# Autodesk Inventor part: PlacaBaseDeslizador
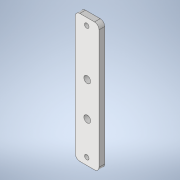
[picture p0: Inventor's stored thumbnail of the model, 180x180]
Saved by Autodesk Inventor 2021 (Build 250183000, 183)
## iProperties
Created: 2021-02
Part Number: PlacaBaseDeslizador
Material: Genérico
Document SubType Name: Modeling
Designer: ATOUZA
Density: 1 g/cm^3
Appearance: Valor por defecto
Author: ATOUZA
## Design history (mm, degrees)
node "Plano de trabajo1"
sketch "Boceto1"
  geometry: L1 (6.426, -37)-(6.426, 37) reference; L2 (5.426, 38)-(0.676, 38) reference; L3 (0.676, 38)-(0.676, 36.1) reference; L4 (0.676, 36.1)-(1.926, 36.1) reference; L5 (1.926, 36.1)-(1.926, 33.4) reference; L6 (1.926, 33.4)-(-4.074, 33.4) reference; L7 (-4.074, 33.4)-(-4.074, 36.1) reference; L8 (-4.074, 36.1)-(-2.824, 36.1) reference; L9 (-2.824, 36.1)-(-2.824, 38) reference; L10 (-2.824, 38)-(-5.074, 38) reference; L11 (-6.074, 37)-(-6.074, -37) reference; L12 (-5.074, -38)-(-2.824, -38) reference; L13 (-2.824, -38)-(-2.824, -36.1) reference; L14 (-2.824, -36.1)-(-4.074, -36.1) reference; L15 (-4.074, -36.1)-(-4.074, -33.4) reference; L16 (-4.074, -33.4)-(1.926, -33.4) reference; L17 (1.926, -33.4)-(1.926, -36.1) reference; L18 (1.926, -36.1)-(0.676, -36.1) reference; L19 (0.676, -36.1)-(0.676, -38) reference; L20 (0.676, -38)-(5.426, -38) reference; L21 (-1.074, -33.4)-(-1.074, 33.4); L22 (-10.098, -50.45)-(10.791, -50.45); L23 (10.791, -50.45)-(10.791, 62); L24 (10.791, 62)-(-10.098, 62); L25 (-10.098, 62)-(-10.098, -50.45); L26 (-404.324, -44.225)-(45.676, -44.225) reference; L27 (-404.324, 55.775)-(45.676, 55.775) reference; C1 r 4.75 at (0.426, -15) reference; C2 r 4.75 at (0.426, 15) reference; C3 r 3 at (0.426, 15); C4 r 3 at (0.426, -15); C5 r 2 at (0, -44.225); C6 r 2 at (0, 55.775); A1 r 1 centre (5.426, 37) between (6.426, 37) and (5.426, 38) reference; A2 r 1 centre (-5.074, 37) between (-5.074, 38) and (-6.074, 37) reference; A3 r 1 centre (-5.074, -37) between (-6.074, -37) and (-5.074, -38) reference; A4 r 1 centre (5.426, -37) between (5.426, -38) and (6.426, -37) reference; 1 further point
  constraints: 10 end point, 4 centre point, 2 coincident, 2 midpoint, 2 parallel, 2 point on line, 1 horizontal, 1 perpendicular
  dimensions: "d0" = 6 diameter of C3; "d1" = 6 diameter of C4; "d2" = 6.225 distance between parallel lines of L12 L26 (derived); "d3" = 12.45 distance between parallel lines of L22 L12; "d4" = 4 diameter of C5; "d6" = 6.225 distance between parallel lines of L27 L24; "d7" = 4 diameter of C6
extrude "Extrusión1" new body sketch "Boceto1" distance "d8" = 5; taper "d9" = 0 deg
fillet "Empalme1" dims "d10" = 4
node "Sólido1"
node "Referencia1"
node "Referencia2"
node "Referencia3"
